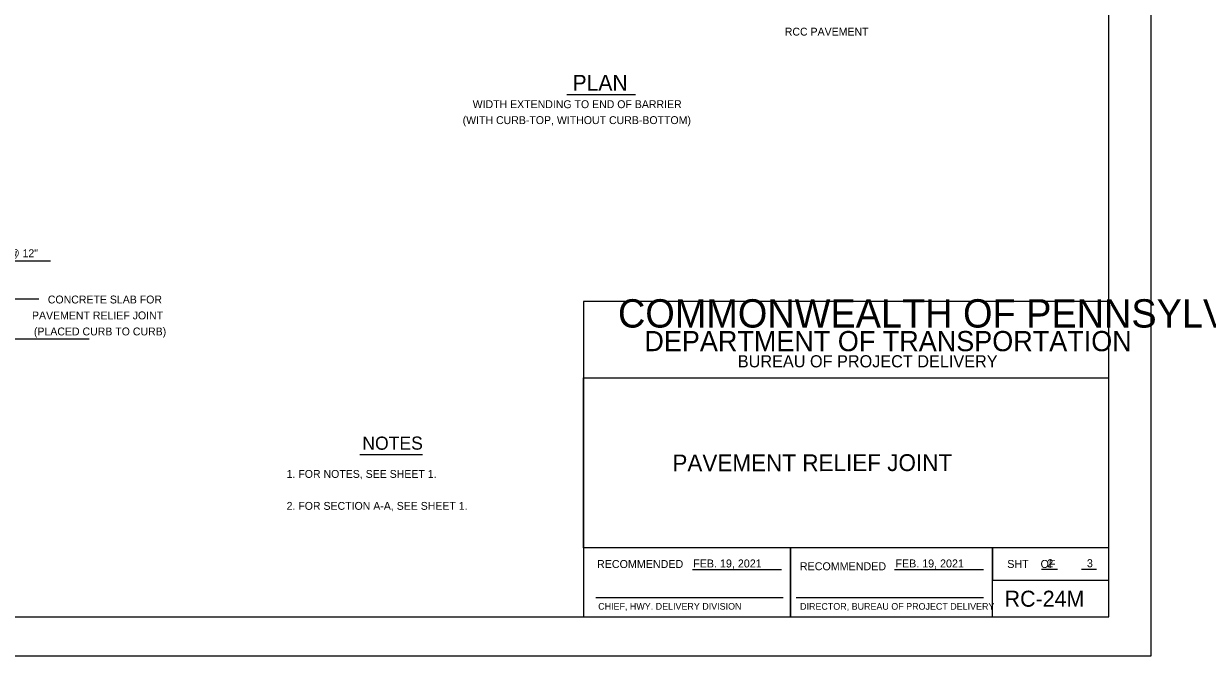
# Model space of a CAD drawing. Extents: x 2084213 to 2099800, y 976677 to 981262.
# Drawn here: x 2095426 to 2096905, y 976677 to 977467 of the extents above; entities that cross this region are included whole.
import ezdxf

# ---------------------------------------------------------------- set-up
doc = ezdxf.new("R2010")
doc.units = 0
doc.layers.add('1', color=7, linetype='Continuous')
doc.layers.add('PLT-BNDY', color=7, linetype='Continuous')

msp = doc.modelspace()

# ---------------------------------------------------------------- linework, layer by layer
at = {"layer": '1'}
for p, q in [((2096104.6, 977378.9), (2096190.7, 977378.9)), ((2095459.7, 977170.9), (2095388.1, 977170.8)), ((2095406.1, 977123.5), (2095445, 977123.5)), ((2095246.4, 977073.7), (2095498.2, 977073.7)), ((2095498.2, 977073.7), (2095508, 977073.7)), ((2095846.3, 976929.2), (2095924.5, 976929.2)), ((2096261.5, 976785.5), (2096372.7, 976785.5)), ((2096514.1, 976785.5), (2096625.2, 976785.5)), ((2096697.7, 976786.1), (2096717.8, 976786.1)), ((2096747.7, 976786.1), (2096766.5, 976786.1)), ((2096141.1, 976750.5), (2096374.8, 976750.5)), ((2096391, 976750.5), (2096625, 976750.5)), ((2096834.1, 976677.3), (2096834.1, 976677.3))]:
    msp.add_line(p, q, dxfattribs=at)
msp.add_lwpolyline([(2096781.6, 976726.5), (2096781.6, 978576.9), (2094202.9, 978576.9), (2094202.9, 976726.5), (2096781.6, 976726.5), (2096781.6, 976812.9), (2096125.4, 976812.9), (2096125.4, 977025.1), (2096781.6, 977025.1), (2096781.6, 977120.2), (2096125.4, 977120.2), (2096125.4, 976726.5), (2096384, 976726.5), (2096384, 976812.9), (2096384, 976726.5), (2096636.6, 976726.5), (2096636.6, 976812.9), (2096636.6, 976772.5), (2096781.6, 976772.5)], dxfattribs=at)
at = {"layer": 'PLT-BNDY'}
msp.add_lwpolyline([(2094074.9, 978626.1), (2096834.1, 978626.1), (2096834.1, 976677.3), (2094074.9, 976677.3)], close=True, dxfattribs=at)

# ---------------------------------------------------------------- texts
at = {"layer": '1'}
for s, height, p in [('RCC PAVEMENT', 9.843, (2096377, 977452.4)), ('PLAN', 19.69, (2096111.9, 977383.7)), ('WIDTH EXTENDING TO END OF BARRIER', 9.843, (2095987.1, 977361.8)), ('(WITH CURB-TOP, WITHOUT CURB-BOTTOM)', 9.843, (2095974.6, 977341.9)), ('#4 @ 12"', 9.84, (2095389.5, 977175.7)), ('CONCRETE SLAB FOR', 9.843, (2095456.4, 977117.9)), ('COMMONWEALTH OF PENNSYLVANIA', 35.379, (2096168.6, 977087.8)), ('PAVEMENT RELIEF JOINT', 9.843, (2095436.6, 977098)), ('(PLACED CURB TO CURB)', 9.843, (2095439, 977078)), ('DEPARTMENT OF TRANSPORTATION', 25.211, (2096201.6, 977058.3)), ('BUREAU OF PROJECT DELIVERY', 15.164, (2096318.3, 977038.1)), ('1. FOR NOTES, SEE SHEET 1.', 9.843, (2095754.7, 976900.1)), ('2. FOR SECTION A-A, SEE SHEET 1.', 9.843, (2095754.7, 976860.2)), ('RECOMMENDED', 10, (2096142.4, 976787.5)), ('FEB. 19, 2021', 10, (2096262.6, 976788.2)), ('RECOMMENDED', 10, (2096395.8, 976784.7)), ('FEB. 19, 2021', 10, (2096515.2, 976788.2)), ('SHT    OF  ', 10, (2096654.9, 976787.6)), ('2', 10, (2096704.8, 976788.5)), ('3', 10, (2096754.4, 976788.5)), ('APPROVED', 0.063, (2096266.6, 976785.3)), ('RC-24M', 20, (2096651.6, 976739.2)), ('CHIEF, HWY. DELIVERY DIVISION', 8.333, (2096143.9, 976735.5)), ('DIRECTOR, BUREAU OF PROJECT DELIVERY', 8.333, (2096396.1, 976735.4))]:
    msp.add_text(s, height=height, dxfattribs=at).set_placement(p)
for s, height, p in [('NOTES', 16.4, (2095849.3, 976935.2)), ('PAVEMENT RELIEF JOINT', 20.997, (2096236.6, 976908.2))]:
    msp.add_text(s, height=height, rotation=0.0819, dxfattribs=at).set_placement(p)

doc.saveas('drawing.dxf')
